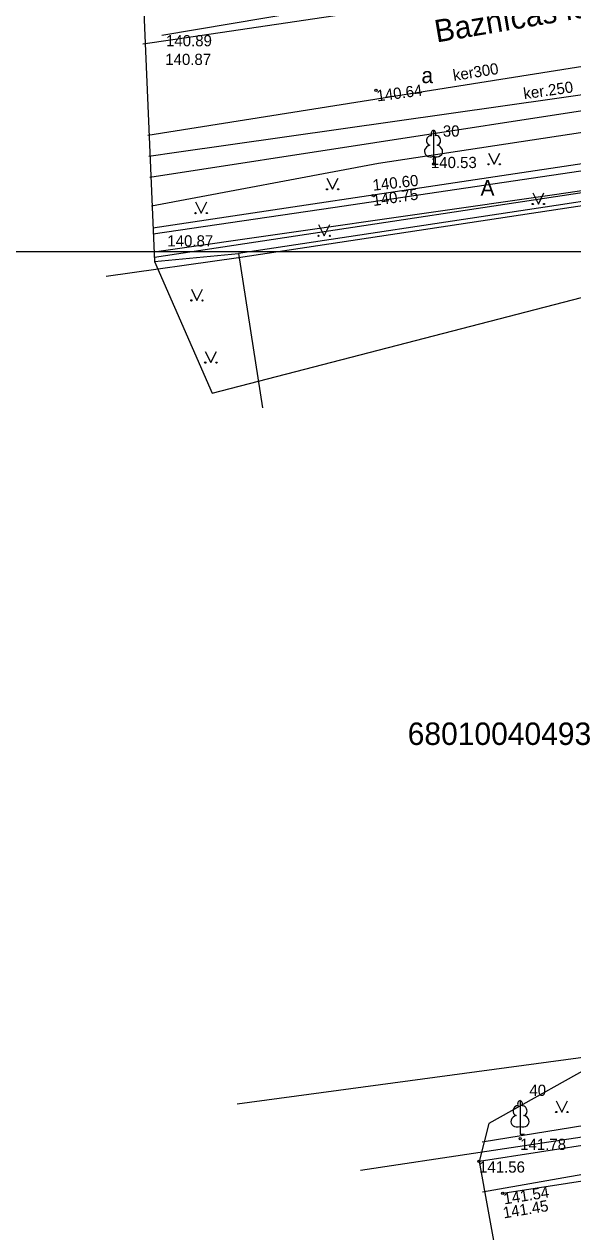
# Model space of a CAD drawing. Extents: x 728710 to 728960, y 272811 to 273475.
# Drawn here: x 728768.6 to 728793.1, y 273158.4 to 273212.2 of the extents above; entities that cross this region are included whole.
import ezdxf

# ---------------------------------------------------------------- set-up
doc = ezdxf.new("R2010")
doc.units = 0
for name, color, linetype in [('Level 17', 7, 'Continuous'), ('Level 18', 7, 'Continuous'), ('Level 19', 7, 'Continuous'), ('Level 21', 7, 'Continuous'), ('Level 23', 7, 'Continuous'), ('Level 27', 7, 'Continuous'), ('Level 3', 7, 'Continuous'), ('Level 38', 7, 'Continuous'), ('Level 4', 7, 'Continuous'), ('Level 41', 7, 'Continuous'), ('Level 42', 7, 'Continuous'), ('Level 45', 7, 'Continuous'), ('Level 48', 7, 'Continuous'), ('Level 54', 7, 'Continuous'), ('Level 57', 7, 'Continuous'), ('Level 58', 7, 'Continuous'), ('Level 60', 7, 'Continuous'), ('RAMI_PLAN_####_TKST_#', 7, 'Continuous'), ('RAMI_UZMR_####_####_#', 7, 'Continuous'), ('RELJ_NOGA_####_####_#', 7, 'Continuous'), ('RELJ_NOGL_####_####_#', 7, 'Continuous'), ('ROBZ_ELEM_####_####_#', 7, 'Continuous'), ('ROBZ_KADS_####_TKST_#', 7, 'Continuous'), ('ROBZ_UZMR_####_####_#', 7, 'Continuous'), ('TERT_KONT_####_####_#', 7, 'Continuous')]:
    doc.layers.add(name, color=color, linetype=linetype)

msp = doc.modelspace()

# ---------------------------------------------------------------- linework, layer by layer
at = {"layer": 'Level 17'}
msp.add_line((728774.223, 273205.388), (728796.151, 273208.761), dxfattribs=at)
at = {"layer": 'Level 18'}
msp.add_lwpolyline([(728775.408, 273206.499), (728828.88, 273214.109)], dxfattribs=at)
at = {"layer": 'Level 19'}
msp.add_lwpolyline([(728774.172, 273206.324), (728775.408, 273206.499)], dxfattribs=at)
at = {"layer": 'Level 21'}
msp.add_line((728807.375, 273163.351), (728789.039, 273160.124), dxfattribs=at)
at = {"layer": 'Level 23'}
msp.add_lwpolyline([(728828.61, 273215.701), (728797.551, 273210.954), (728774.123, 273207.246)], dxfattribs=at)
at = {"layer": 'Level 27'}
msp.add_lwpolyline([(728774.426, 273201.627), (728778.173, 273201.979)], dxfattribs=at)
at = {"layer": 'Level 3'}
for p, q in [((728798.835, 273205.109), (728792.334, 273204.124)), ((728792.334, 273204.124), (728778.173, 273201.979)), ((728778.173, 273201.979), (728779.239, 273195.1))]:
    msp.add_line(p, q, dxfattribs=at)
at = {"layer": 'Level 38'}
msp.add_line((728806.316, 273162.585), (728789.945, 273160.073), dxfattribs=at)
at = {"layer": 'Level 4'}
for p, q in [((728790.803, 273205.597), (728799.004, 273206.826)), ((728774.345, 273203.129), (728790.803, 273205.597)), ((728795.195, 273205.024), (728792.259, 273204.602)), ((728792.259, 273204.602), (728774.404, 273202.033)), ((728805.357, 273164.023), (728788.892, 273161.497))]:
    msp.add_line(p, q, dxfattribs=at)
at = {"layer": 'Level 41'}
for points in [[(728792.122, 273205.478), (728819.326, 273209.502), (728829.414, 273210.952)], [(728774.36, 273202.851), (728782.379, 273204.037), (728792.122, 273205.478)]]:
    msp.add_lwpolyline(points, dxfattribs=at)
at = {"layer": 'Level 42'}
msp.add_lwpolyline([(728773.902, 273211.333), (728775.244, 273211.516), (728790.816, 273213.839)], dxfattribs=at)
at = {"layer": 'Level 45'}
for points in [[(728774.752, 273211.72), (728796.297, 273215.351), (728797.897, 273216.42)], [(728799.011, 273206.827), (728795.279, 273207.647), (728784.404, 273206), (728774.293, 273204.089)]]:
    msp.add_lwpolyline(points, dxfattribs=at)
at = {"layer": 'Level 48'}
for centre in [(728784.295, 273209.255), (728786.863, 273205.967), (728784.159, 273204.568), (728790.725, 273162.507), (728788.892, 273161.497), (728789.945, 273160.073)]:
    msp.add_circle(centre, 0.05, dxfattribs=at)
at = {"layer": 'RAMI_PLAN_####_TKST_#'}
for points in [[(728728.89, 273202.048), (728728.89, 273475.126), (728912.915, 273475.126), (728912.915, 273202.048)], [(728709.938, 272811.037), (728959.516, 272811.036), (728959.516, 273202.048), (728709.939, 273202.048)]]:
    msp.add_lwpolyline(points, close=True, dxfattribs=at)
at = {"layer": 'RAMI_UZMR_####_####_#'}
msp.add_lwpolyline([(728776.746, 273299.712), (728774.767, 273288.109), (728769.195, 273286.654), (728770.672, 273271.11), (728776.42, 273245.146), (728778.568, 273229.68), (728773.046, 273228.469), (728773.87, 273214.498), (728774.426, 273201.627), (728776.99, 273195.753), (728795.127, 273200.451), (728799.264, 273172.386), (728794.758, 273166.22), (728789.327, 273163.194), (728788.892, 273161.497), (728790.999, 273149.932)], dxfattribs=at)
at = {"layer": 'RELJ_NOGL_####_####_#'}
msp.add_lwpolyline([(728789.033, 273162.366), (728794.798, 273163.301)], dxfattribs=at)
at = {"layer": 'ROBZ_ELEM_####_####_#'}
for points in [[(728799.369, 273205.575), (728774.417, 273201.799)], [(728804.76, 273167.644), (728778.115, 273164.054)]]:
    msp.add_lwpolyline(points, dxfattribs=at)
at = {"layer": 'ROBZ_UZMR_####_####_#'}
for p, q in [((728798.857, 273204.918), (728778.166, 273201.794)), ((728778.166, 273201.794), (728772.264, 273200.961)), ((728783.605, 273161.103), (728804.732, 273164.296))]:
    msp.add_line(p, q, dxfattribs=at)
at = {"layer": 'TERT_KONT_####_####_#'}
for p, q in [((728786.863, 273206.314), (728786.863, 273205.967)), ((728789.315, 273206.458), (728789.565, 273205.958)), ((728789.565, 273205.958), (728789.815, 273206.458)), ((728786.863, 273205.967), (728787.063, 273205.967)), ((728782.113, 273205.343), (728782.363, 273204.843)), ((728782.363, 273204.843), (728782.613, 273205.343)), ((728791.287, 273204.687), (728791.537, 273204.187)), ((728791.537, 273204.187), (728791.787, 273204.687)), ((728776.253, 273204.284), (728776.503, 273203.784)), ((728776.503, 273203.784), (728776.753, 273204.284)), ((728781.737, 273203.268), (728781.987, 273202.768)), ((728781.987, 273202.768), (728782.237, 273203.268)), ((728776.066, 273200.389), (728776.316, 273199.889)), ((728776.316, 273199.889), (728776.566, 273200.389)), ((728776.687, 273197.617), (728776.937, 273197.117)), ((728776.937, 273197.117), (728777.187, 273197.617)), ((728792.333, 273164.199), (728792.583, 273163.699)), ((728792.583, 273163.699), (728792.833, 273164.199)), ((728790.718, 273163.053), (728790.718, 273162.706)), ((728790.718, 273162.706), (728790.918, 273162.706))]:
    msp.add_line(p, q, dxfattribs=at)
for points in [[(728786.863, 273207.467), (728786.863, 273206.314)], [(728786.952, 273207.234), (728786.951, 273207.235)], [(728790.718, 273164.206), (728790.718, 273163.053)], [(728790.808, 273163.974), (728790.807, 273163.975)]]:
    msp.add_lwpolyline(points, dxfattribs=at)
for centre, radius in [((728789.315, 273205.958), 0.028), ((728789.815, 273205.958), 0.0263), ((728782.112, 273204.842), 0.028), ((728782.612, 273204.842), 0.0263), ((728791.286, 273204.187), 0.028), ((728791.786, 273204.187), 0.0263), ((728776.253, 273203.784), 0.028), ((728776.753, 273203.784), 0.0263), ((728781.737, 273202.768), 0.028), ((728782.237, 273202.768), 0.0263), ((728776.066, 273199.888), 0.028), ((728776.566, 273199.888), 0.0263), ((728776.687, 273197.116), 0.028), ((728777.187, 273197.116), 0.0263), ((728792.333, 273163.699), 0.028), ((728792.833, 273163.699), 0.0263)]:
    msp.add_circle(centre, radius, dxfattribs=at)
for centre, major_axis, ratio, start_param, end_param in [((728786.863, 273207.317), (0, -0.15), 0.707107, 3.14537, 5.287485), ((728786.863, 273207.317), (0, -0.15), 0.707107, 0.995701, 3.137816), ((728786.773, 273206.56), (0.307, 0.095), 0.814445, 1.570796, 4.752015), ((728786.735, 273207.022), (-0.039, -0.212), 0.861323, 3.141593, 6.283185), ((728786.952, 273206.56), (-0.307, 0.095), 0.814445, 1.531171, 4.712389), ((728786.991, 273207.022), (0.039, -0.212), 0.861323, 0, 3.141593), ((728790.59, 273163.761), (-0.039, -0.212), 0.861323, 3.141593, 6.283185), ((728790.718, 273164.056), (0, -0.15), 0.707107, 3.14537, 5.287485), ((728790.718, 273164.056), (0, -0.15), 0.707107, 0.995701, 3.137816), ((728790.846, 273163.761), (0.039, -0.212), 0.861323, 0, 3.141593), ((728790.628, 273163.299), (0.307, 0.095), 0.814445, 1.570796, 4.752015), ((728790.808, 273163.299), (-0.307, 0.095), 0.814445, 1.531171, 4.712389)]:
    msp.add_ellipse(centre, major_axis=major_axis, ratio=ratio, start_param=start_param, end_param=end_param, dxfattribs=at)

# ---------------------------------------------------------------- texts
at = {"layer": 'Level 54'}
msp.add_text('Baznīcas iela', height=1, rotation=9.6084, dxfattribs=at).set_placement((728786.999, 273211.385))
at = {"layer": 'Level 57'}
for s, p in [(' 140.89', (728774.752, 273211.22)), (' 140.87', (728774.717, 273210.387)), ('140.53', (728786.745, 273205.79)), (' 140.87', (728774.811, 273202.293)), ('141.78', (728790.725, 273162.007)), ('141.56', (728788.892, 273160.997))]:
    msp.add_text(s, height=0.5, dxfattribs=at).set_placement(p)
for s, rotation, p in [('140.64', 7.454, (728784.36, 273208.759)), ('140.60', 6.303, (728784.177, 273204.778)), ('140.75', 8.4136, (728784.184, 273204.094)), ('141.54', 8.8664, (728790.022, 273159.579)), ('141.45', 9.4698, (728789.998, 273158.953))]:
    msp.add_text(s, height=0.5, rotation=rotation, dxfattribs=at).set_placement(p)
at = {"layer": 'Level 58'}
for s, p in [('a', (728786.324, 273209.577)), ('A', (728788.957, 273204.555))]:
    msp.add_text(s, height=0.7, dxfattribs=at).set_placement(p)
at = {"layer": 'Level 60'}
msp.add_text('ker300', height=0.5, rotation=8.993, dxfattribs=at).set_placement((728787.769, 273209.672))
at = {"layer": 'RAMI_PLAN_####_TKST_#'}
msp.add_text('ker.250', height=0.5, rotation=8.1003, dxfattribs=at).set_placement((728790.906, 273208.856))
at = {"layer": 'RELJ_NOGA_####_####_#'}
for s, p in [('30', (728787.278, 273207.193)), ('40', (728791.136, 273164.419))]:
    msp.add_text(s, height=0.5, dxfattribs=at).set_placement(p)
at = {"layer": 'ROBZ_KADS_####_TKST_#'}
msp.add_text('68010040493', height=1, dxfattribs=at).set_placement((728785.711, 273180.067))

doc.saveas('drawing.dxf')
